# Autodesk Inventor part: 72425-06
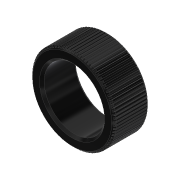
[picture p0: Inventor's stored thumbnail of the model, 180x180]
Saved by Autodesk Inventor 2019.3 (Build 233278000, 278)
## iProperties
Created: 2013-06
Part Number: 72425-06
Material: Ogólny
Document SubType Name: Modeling
Designer: CADENGINEERING4
Density: 1 g/cm^3
Appearance: Gładki — czarny
Author: CADENGINEERING4
Revision Number: ÈÎºÎ
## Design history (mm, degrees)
feature "ÊäÈë1"
node "Bryła1"
